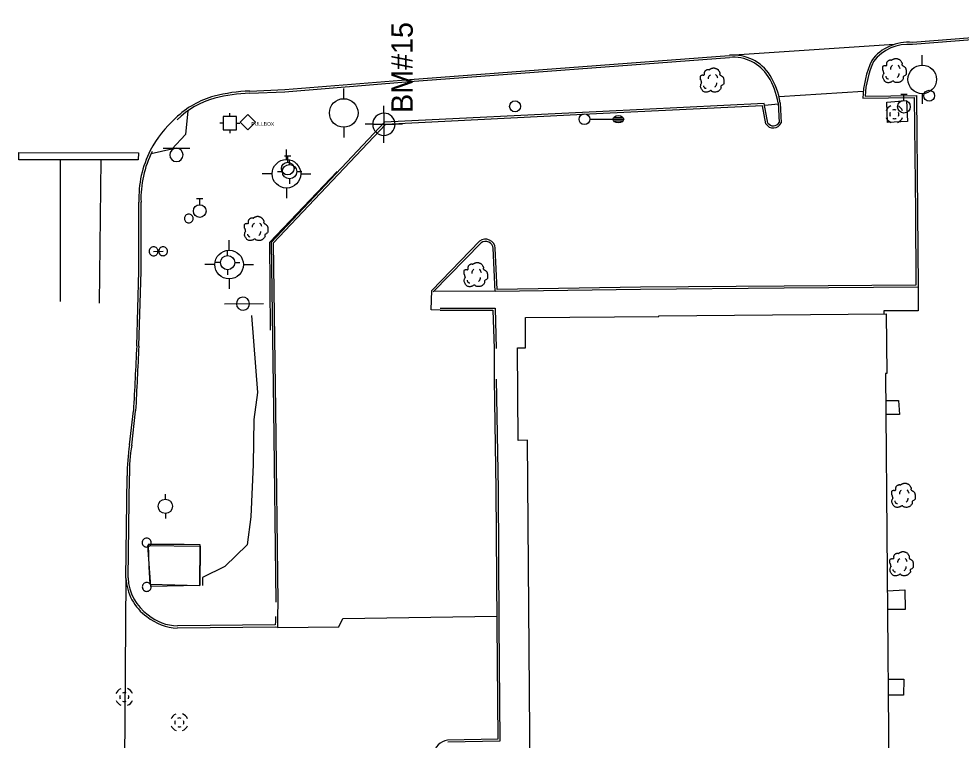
# Model space of a CAD drawing. Extents: x 2145380 to 2156929, y 139568 to 149130.
# Drawn here: x 2145641 to 2145904.9, y 142715.7 to 142917.6 of the extents above; entities that cross this region are included whole.
import ezdxf

# ---------------------------------------------------------------- set-up
doc = ezdxf.new("R2010")
doc.units = 0
for name, color, linetype in [('Default', 7, 'Continuous'), ('SURV_Benchmark', 7, 'Continuous'), ('SURV_Text', 7, 'Continuous'), ('TOPO_Asphalt', 7, 'Continuous'), ('TOPO_Building', 7, 'Continuous'), ('TOPO_Concrete', 7, 'Continuous'), ('TOPO_Curb Back', 7, 'Continuous'), ('TOPO_DRAIN_Inlet Grate', 7, 'Continuous'), ('TOPO_DRAIN_Manhole', 7, 'Continuous'), ('TOPO_Flowline', 7, 'Continuous'), ('TOPO_Light Pole', 7, 'Continuous'), ('TOPO_Misc', 7, 'Continuous'), ('TOPO_Misc Line', 7, 'Continuous'), ('TOPO_Power Pole', 7, 'Continuous'), ('TOPO_Power Pullbox', 7, 'Continuous'), ('TOPO_Sidewalk', 7, 'Continuous'), ('TOPO_Sign', 7, 'Continuous'), ('TOPO_Traffic Signal', 7, 'Continuous'), ('TOPO_Tree', 7, 'Continuous'), ('TOPO_Wall Freestanding', 7, 'Continuous'), ('TOPO_Water Fire Hydrant', 7, 'Continuous'), ('TOPO_Water Meter', 7, 'Continuous'), ('TOPO_Water Valve', 7, 'Continuous')]:
    doc.layers.add(name, color=color, linetype=linetype)

# ---------------------------------------------------------------- blocks, each defined once
blk = doc.blocks.new('MHEXST')
at = {"layer": 'TOPO_DRAIN_Manhole'}
for centre, radius, start, end in [((-0.1, 0.3), 12.7, 112.9748, 158.2636), ((-0.1, 0.1), 6.35, 157.9722, 204.161), ((-0.1, 0.1), 6.35, 66.1941, 113.691), ((-0.1, 0.3), 12.7, 22.0744, 68.6991), ((-0.1, 0.1), 6.35, 336.8023, 21.4046), ((-0.1, 0.3), 12.7, 202.6921, 248.1938), ((-0.1, 0.1), 6.35, 248.5791, 293.1995), ((-0.1, 0.3), 12.7, 291.7963, 337.3032)]:
    blk.add_arc(centre, radius, start, end, dxfattribs=at)
blk = doc.blocks.new('TRFSIG')
at = {"layer": 'TOPO_Traffic Signal'}
for p, q in [((0.04, 4.66), (0.04, 7.04)), ((-4.7, -0.09), (-7.08, -0.09)), ((0.04, -4.83), (0.04, -7.22)), ((4.79, -0.09), (7.17, -0.09))]:
    blk.add_line(p, q, dxfattribs=at)
blk.add_lwpolyline([(-4.7, -4.85), (4.81, -4.83), (4.79, 4.67), (-4.72, 4.66), (-4.7, -4.85)], dxfattribs=at)
blk = doc.blocks.new('FIRHYD')
at = {"layer": 'TOPO_Water Fire Hydrant'}
for p, q in [((-0.02, 10.16), (-0.03, 17.34)), ((10.16, 0.02), (17.34, 0.03)), ((-10.16, -0.02), (-17.34, -0.03)), ((0.02, -10.16), (0.03, -17.34))]:
    blk.add_line(p, q, dxfattribs=at)
blk.add_circle((0, 0), 10.16, dxfattribs=at)
blk = doc.blocks.new('POST')
at = {"layer": 'TOPO_Misc'}
for start, end in [(89.99996, 180.00004), (179.99996, 270.00004), (359.99996, 90.00004), (269.99996, 0.00004)]:
    blk.add_arc((-0.01, 0.03), 3.16, start, end, dxfattribs=at)
blk = doc.blocks.new('POWPOL')
at = {"layer": 'TOPO_Power Pole'}
for p, q in [((0, 10.16), (0, 17.34)), ((0, -10.16), (0, -17.34))]:
    blk.add_line(p, q, dxfattribs=at)
blk.add_circle((0, 0), 10.16, dxfattribs=at)
blk = doc.blocks.new('LP')
at = {"layer": 'TOPO_Light Pole'}
blk.add_line((3.81, 0), (20.32, 0), dxfattribs=at)
for points in [[(20.32, 0), (27.94, 0)], [(20.32, 0), (23.5, 0)], [(20.83, 1.27), (27.43, 1.27)], [(20.83, 1.27), (23.5, 1.27)], [(23.71, 1.27), (27.43, 1.27)], [(23.71, 0), (27.94, 0)], [(20.83, -1.27), (27.43, -1.27)], [(20.83, -1.27), (23.5, -1.27)], [(23.71, -1.27), (27.43, -1.27)]]:
    blk.add_lwpolyline(points, dxfattribs=at)
blk.add_circle((0, 0), 3.81, dxfattribs=at)
blk.add_ellipse((24.13, 0), major_axis=(3.81, 0), ratio=0.666667, dxfattribs=at)
blk = doc.blocks.new('TREE')
at = {"layer": 'TOPO_Tree'}
for points in [[(-14.1, -0.4), (-14.2, 0.5), (-14.4, 1.4), (-14.6, 2.3), (-14.8, 3.2), (-15.5, 4), (-15.7, 4.9), (-15.8, 5.6), (-15.7, 6.3), (-15.7, 7), (-15.6, 7.9), (-15.7, 8.8), (-15.1, 9.7), (-14.6, 10.4), (-13.8, 10.5), (-13, 10.7), (-12.2, 11), (-11.1, 10), (-10.4, 10.7), (-9.4, 11.7), (-10.3, 13.3), (-9.8, 14.4), (-9.6, 15.1), (-9.3, 15.9), (-8.8, 16.5), (-8.2, 17.3), (-7.5, 17.7), (-6.7, 18.1), (-6.1, 18.4), (-5.6, 18.6), (-5.1, 18.7), (-4.5, 18.7), (-4, 18.5), (-3.5, 18.1)], [(-3.5, 17.6), (-3.1, 18.3), (-2.6, 18.8), (-1.9, 19.2), (-1, 19.7), (-0.2, 20), (0.7, 20.2), (1.6, 20.5), (2.5, 20.8), (3.4, 20.8), (4.1, 20.7), (4.8, 20.5), (5.5, 20.2), (6.4, 19.9), (7.3, 19.7), (8.2, 19.2), (9.4, 18.4), (10, 17.2), (10.8, 16), (11.2, 15.3), (11.6, 14.6), (11.9, 13.9), (12.2, 13.1), (11.4, 12), (11.9, 11.2), (12, 11), (12.2, 10.9), (12.4, 10.7), (12.9, 10.4), (13.5, 10), (14, 9.7), (14.7, 9.2), (15.4, 8.7), (16.1, 8.1), (16.7, 7.5), (16.9, 6.7), (17.1, 6), (17.6, 4.4), (17.7, 2.8), (17.7, 1.2), (17.7, -0.2), (17.8, -2.2), (16.6, -3), (15.5, -3.8), (14.3, -4.6), (13.2, -5.3)], [(13.2, -5.3), (13.3, -5.8), (13.4, -6.3), (13.4, -6.7), (13.8, -8.5), (12.2, -10), (10.8, -11.5), (10, -12.3), (9.1, -12.8), (8.2, -13.1), (6, -13.8), (3.3, -13.6), (1.3, -13.1), (0.5, -12.9), (-0.1, -11.4), (-0.8, -11.5), (-2, -11.6), (-3.3, -12.8), (-4.5, -13.1), (-6.1, -13.5), (-7.8, -14), (-9.3, -13.6), (-11.4, -13.1), (-12.8, -11.4), (-14.1, -9.4), (-15.3, -7.3), (-15.6, -5.1), (-15.1, -3), (-14.9, -1.9), (-13.9, -0.8), (-13.5, 0.1)], [(-4.2, 5.1), (-4.5, 6.1), (-4.3, 7.2), (-3.8, 8.2), (-3.3, 9.3), (-2.7, 10.3), (-1.6, 11)], [(5.9, 11.2), (6.5, 10.7), (7, 10.2), (7.4, 9.5), (7.9, 8.6), (8.3, 7.6), (8.5, 6.6)], [(-11.4, -4.5), (-11.5, -5.4), (-11, -6.3), (-10.1, -7.2), (-9.3, -8), (-8.5, -8.3), (-7.7, -8.1)], [(4.8, -6.3), (5.7, -5.7), (6.3, -4.9), (6.8, -3.9), (7.4, -2.8), (7.6, -1.7), (7.5, -0.6)]]:
    blk.add_open_spline(points, degree=3, dxfattribs=at)
blk = doc.blocks.new('pulbox')
at = {"layer": 'Default'}
blk.add_lwpolyline([(-5.38, -0.01), (-0.02, 5.42), (5.4, 0.06), (0.05, -5.36), (-5.38, -0.01)], dxfattribs=at)
blk.add_text('PULLBOX', height=2.54, dxfattribs=at).set_placement((2.54, -2.54))
blk = doc.blocks.new('WTRMTR')
at = {"layer": 'Default'}
blk.add_circle((0, 0), 3.89, dxfattribs=at)
blk = doc.blocks.new('WATVAL')
at = {"layer": 'Default'}
for p, q in [((-2.25, 9), (2.25, 9)), ((0, 4.5), (0, 9))]:
    blk.add_line(p, q, dxfattribs=at)
blk.add_circle((0, 0), 4.5, dxfattribs=at)
blk = doc.blocks.new('BM')
at = {"layer": 'SURV_Benchmark'}
for p, q in [((0, 2.49), (0, 4.15)), ((-2.49, 0), (-4.16, 0)), ((4.16, 0), (2.49, 0)), ((0, -4.16), (0, -2.49))]:
    blk.add_line(p, q, dxfattribs=at)
for points in [[(0, 2.49), (0, 2.49), (0, 0), (2.49, 0), (2.49, 0), (2.49, 0)], [(0, 2.49), (0, 2.49), (0, 0), (2.49, 0), (2.49, 0), (2.49, 0), (2.49, 0)], [(-2.5, 0), (-2.49, 0), (0, 0), (0, -2.49), (0, -2.49)], [(-2.5, 0), (-2.49, 0), (0, 0), (0, -2.49), (0, -2.49)]]:
    blk.add_lwpolyline(points, dxfattribs=at)
for start, end in [(90.0638, 180.0068), (0.0638, 90.0068), (0.0638, 90.0068), (180.0638, 270.0068), (180.0638, 270.0068), (269.9472, 359.9927)]:
    blk.add_arc((0, 0), 2.5, start, end, dxfattribs=at)

msp = doc.modelspace()

# ---------------------------------------------------------------- linework, layer by layer
at = {"layer": 'TOPO_Asphalt'}
for p, q in [((2145886.13, 142910.45), (2145841.37, 142907.47)), ((2145877.51, 142897.29), (2145853.93, 142895.76)), ((2145774.14, 142825.35), (2145774.11, 142816.75)), ((2145671.02, 142761.1), (2145670.5, 142699.12)), ((2145713.58, 142754.35), (2145713.49, 142750.35))]:
    msp.add_line(p, q, dxfattribs=at)
for points in [[(2145759.07, 142836.04), (2145756.5, 142836.19), (2145756.67, 142841.6)], [(2145713.48, 142747.28), (2145730.63, 142747.43), (2145731.81, 142749.72), (2145774.89, 142750.39)]]:
    msp.add_lwpolyline(points, dxfattribs=at)
msp.add_arc((2145705.41, 142866.44), 31.07, 131.2509, 152.4834, dxfattribs=at)
at = {"layer": 'TOPO_Building'}
msp.add_lwpolyline([(2145884.64, 142706.75), (2145784.22, 142705.97), (2145783.49, 142799.65), (2145780.88, 142799.63), (2145780.68, 142825.53), (2145782.96, 142825.55), (2145782.9, 142834.03), (2145820.28, 142834.32), (2145820.28, 142834.52), (2145883.96, 142835.02), (2145884.09, 142818.36), (2145883.77, 142818.35)], close=True, dxfattribs=at)
at = {"layer": 'TOPO_Concrete'}
for p in [(2145849.96, 142893.38), (2145853.67, 142893.7)]:
    msp.add_line(p, (2145849.97, 142893.35), dxfattribs=at)
for points in [[(2145884.29, 142888.65), (2145884.12, 142894.3), (2145889.62, 142894.74), (2145889.85, 142888.86), (2145884.29, 142888.65)], [(2145691.76, 142759.04), (2145678.01, 142758.73), (2145677.16, 142770.2), (2145691.84, 142769.99), (2145691.76, 142759.04)], [(2145687.34, 142770.51), (2145677.29, 142770.48), (2145677.43, 142764.27), (2145677.71, 142759.42), (2145691.77, 142759.01)]]:
    msp.add_lwpolyline(points, dxfattribs=at)
at = {"layer": 'TOPO_Curb Back'}
for points in [[(2146086.5, 142923.91), (2146062.14, 142922.81), (2146006.06, 142919.37), (2145953.33, 142915.85), (2145891.26, 142911.02)], [(2146086.5, 142923.31), (2146062.17, 142922.21), (2146006.1, 142918.78), (2145953.37, 142915.25), (2145891.26, 142910.41)], [(2145705.69, 142897.41), (2145715.49, 142897.82), (2145750.51, 142900.64), (2145840, 142907.41)], [(2145705.71, 142896.81), (2145715.53, 142897.22), (2145750.55, 142900.04), (2145840.06, 142906.82)], [(2145878.01, 142895.99), (2145892.37, 142896.17), (2145892.74, 142863.48), (2145892.85, 142842.52), (2145855.35, 142842.22), (2145815.14, 142841.9), (2145774.4, 142841.27), (2145773.86, 142853.39)], [(2145850.79, 142888.46), (2145849.77, 142893.91), (2145804.61, 142891.73), (2145743.47, 142888.67), (2145711.71, 142855.05), (2145712.36, 142808.25), (2145712.98, 142754.34)], [(2145850.22, 142888.24), (2145849.28, 142893.29), (2145804.64, 142891.13), (2145743.74, 142888.08), (2145712.31, 142854.81), (2145712.96, 142808.26), (2145713.58, 142754.35)], [(2145877.38, 142895.38), (2145891.78, 142895.57), (2145892.14, 142863.48), (2145892.25, 142843.11), (2145855.35, 142842.82), (2145815.14, 142842.5), (2145774.97, 142841.88), (2145774.46, 142853.43)], [(2145853.65, 142894.1), (2145853.93, 142888.65)], [(2145854.25, 142894.16), (2145854.54, 142888.53)], [(2145711.55, 142830.49), (2145711.32, 142855.13), (2145730.22, 142874.89)], [(2145674.05, 142826.07), (2145674.67, 142847.01), (2145674.66, 142866.3)], [(2145674.65, 142826.04), (2145675.27, 142847), (2145675.26, 142866.31)], [(2145770.08, 142855.38), (2145756.67, 142841.6)], [(2145770.48, 142854.93), (2145757.1, 142841.18)], [(2145759.07, 142836.64), (2145774.39, 142836.67), (2145774.74, 142825.37)], [(2145759.07, 142836.04), (2145773.81, 142836.07), (2145774.14, 142825.35)], [(2145774.11, 142816.75), (2145774.65, 142785.86), (2145774.9, 142748.25), (2145775.16, 142716.03), (2145761.11, 142715.71)], [(2145774.71, 142816.76), (2145775.25, 142785.87), (2145775.5, 142748.26), (2145775.76, 142715.44), (2145761.17, 142715.11)], [(2145672.06, 142798.38), (2145673.14, 142807.9)], [(2145672.65, 142798.3), (2145673.74, 142807.85)], [(2145671.02, 142761.1), (2145671.4, 142789.68)], [(2145671.62, 142761.11), (2145672, 142789.68)], [(2145713.5, 142750.31), (2145713.48, 142747.28), (2145712.97, 142747.32), (2145685.42, 142747.1)], [(2145712.9, 142750.32), (2145712.9, 142748.9), (2145712.86, 142747.98), (2145685.43, 142747.7)]]:
    msp.add_lwpolyline(points, dxfattribs=at)
for centre, radius, start, end in [((2145890.08, 142898.28), 12.8, 84.6897, 142.941), ((2145890.08, 142898.28), 12.2, 84.4518, 142.6291), ((2145841.16, 142895.41), 12.06, 31.8502, 95.4973), ((2145841.16, 142895.41), 11.46, 31.8468, 95.5275), ((2145905.51, 142894.38), 28.15, 155.6481, 177.9548), ((2145905.51, 142894.38), 27.55, 155.788, 176.6443), ((2145834.14, 142890.99), 19.76, 9.0341, 31.9817), ((2145834.14, 142890.99), 20.36, 8.9444, 31.9797), ((2145702.16, 142872.13), 24.69, 105.0623, 134.2848), ((2145707.07, 142852.94), 44.49, 91.7794, 104.7442), ((2145707.07, 142852.94), 43.89, 91.7752, 104.742), ((2145702.16, 142872.13), 24.09, 105.0663, 134.2848), ((2145852.31, 142889.5), 2.43, 211.1477, 336.5758), ((2145852.31, 142889.5), 1.83, 214.3157, 332.4691), ((2145704.6, 142867.3), 29.96, 153.2161, 181.9143), ((2145704.6, 142867.3), 29.36, 153.2161, 181.9334), ((2145771.74, 142853.22), 2.72, 4.3097, 127.5899), ((2145771.74, 142853.22), 2.12, 4.5437, 126.5018), ((2161048.92, 142043.63), 15394.76, 177.086696, 177.154392), ((2161048.93, 142043.63), 15394.17, 177.086673, 177.154463), ((2145721.13, 142790.33), 49.73, 170.6762, 180.7386), ((2145721.13, 142790.33), 49.13, 170.659, 180.7478), ((2145685.07, 142761.73), 14.06, 182.5625, 234.441), ((2145685.07, 142761.73), 13.46, 182.6359, 234.5179), ((2145685.94, 142761.46), 13.78, 230.9156, 267.8614), ((2145685.94, 142761.46), 14.38, 230.9908, 267.9161), ((2145761.93, 142710.85), 4.93, 99.5713, 169.4602)]:
    msp.add_arc(centre, radius, start, end, dxfattribs=at)
at = {"layer": 'TOPO_DRAIN_Inlet Grate'}
msp.add_line((2145678.79, 142852.54), (2145681.45, 142852.55), dxfattribs=at)
at = {"layer": 'TOPO_Flowline'}
msp.add_lwpolyline([(2145706.15, 142834.57), (2145707.84, 142813.02), (2145706.89, 142805.44), (2145706.62, 142792.9), (2145705.97, 142778.22), (2145704.97, 142770.4), (2145698.73, 142764.31), (2145692.47, 142761.25), (2145692.48, 142758.96)], dxfattribs=at)
at = {"layer": 'TOPO_Misc Line'}
for p, q in [((2145652.61, 142878.17), (2145652.64, 142838.47)), ((2145664, 142878.16), (2145663.55, 142838))]:
    msp.add_line(p, q, dxfattribs=at)
msp.add_lwpolyline([(2145641.05, 142880.2), (2145674.51, 142880.15), (2145674.5, 142878.14), (2145641.05, 142878.19)], close=True, dxfattribs=at)
at = {"layer": 'TOPO_Sidewalk'}
msp.add_line((2145774.4, 142841.27), (2145757.32, 142841.4), dxfattribs=at)
for points in [[(2145688.33, 142891.85), (2145687.71, 142885.28), (2145683.92, 142881.18), (2145678.06, 142879.86)], [(2145892.85, 142842.52), (2145892.92, 142835.87), (2145883.23, 142835.92), (2145883.23, 142835.01)], [(2145883.83, 142810.75), (2145887.34, 142810.78), (2145887.61, 142806.89), (2145883.86, 142806.86)], [(2145884.25, 142757.51), (2145889.14, 142757.83), (2145889.25, 142752.3), (2145884.29, 142752.3)], [(2145884.44, 142732.77), (2145888.86, 142732.8), (2145888.82, 142728.29), (2145884.48, 142728.26)]]:
    msp.add_lwpolyline(points, dxfattribs=at)
at = {"layer": 'TOPO_Sign'}
for points in [[(2145681.43, 142881.4), (2145688.93, 142881.4)], [(2145685.18, 142881.4), (2145685.18, 142881.4)], [(2145683.31, 142879.53), (2145683.31, 142879.53)], [(2145685.18, 142877.66), (2145685.18, 142877.66)], [(2145687.05, 142879.53), (2145687.05, 142879.53)], [(2145698.67, 142837.88), (2145709.55, 142837.94)]]:
    msp.add_lwpolyline(points, dxfattribs=at)
for centre, radius, start, end in [((2145685.18, 142879.53), 1.87, 90, 180), ((2145685.18, 142879.53), 1.87, 360, 90), ((2145685.18, 142879.53), 1.87, 180, 270), ((2145685.18, 142879.53), 1.87, 270, 0), ((2145703.81, 142837.9), 1.84, 47.4196, 227.4196), ((2145703.81, 142837.9), 1.84, 227.4196, 47.4196)]:
    msp.add_arc(centre, radius, start, end, dxfattribs=at)
at = {"layer": 'TOPO_Wall Freestanding'}
msp.add_lwpolyline([(2145691.77, 142759.01), (2145691.84, 142770.39), (2145687.34, 142770.51)], dxfattribs=at)

# ---------------------------------------------------------------- block references
at = {"layer": 'SURV_Benchmark', "xscale": 1.25, "yscale": 1.25}
msp.add_blockref('BM', (2145743.27, 142888.11), dxfattribs=at)
at = {"layer": 'TOPO_DRAIN_Manhole', "xscale": 0.19685000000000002, "yscale": 0.19685000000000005}
for p in [(2145886.23, 142890.9), (2145670.59, 142727.74), (2145686.01, 142720.65)]:
    msp.add_blockref('MHEXST', p, dxfattribs=at)
at = {"layer": 'TOPO_Light Pole', "xscale": 0.39370000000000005, "yscale": 0.3937000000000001}
msp.add_blockref('LP', (2145799.42, 142889.53), dxfattribs=at)
at = {"layer": 'TOPO_Misc', "xscale": 0.39370000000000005, "yscale": 0.3937000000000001}
for p in [(2145688.64, 142861.73), (2145678.79, 142852.54), (2145681.45, 142852.55), (2145676.84, 142770.99), (2145676.87, 142758.59)]:
    msp.add_blockref('POST', p, dxfattribs=at)
at = {"layer": 'TOPO_Power Pole'}
for p, xscale, yscale in [((2145894.02, 142900.67), 0.39370000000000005, 0.3937000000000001), ((2145732.02, 142891.28), 0.39370000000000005, 0.3937000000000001), ((2145682.08, 142781.17), 0.19685000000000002, 0.19685000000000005)]:
    msp.add_blockref('POWPOL', p, dxfattribs=dict(at, xscale=xscale, yscale=yscale))
at = {"layer": 'TOPO_Power Pullbox', "xscale": 0.39370000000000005, "yscale": 0.3937000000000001}
msp.add_blockref('pulbox', (2145705.16, 142888.71), dxfattribs=at)
at = {"layer": 'TOPO_Traffic Signal', "xscale": 0.39370000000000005, "yscale": 0.3937000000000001}
msp.add_blockref('TRFSIG', (2145700.11, 142888.46), dxfattribs=at)
at = {"layer": 'TOPO_Tree', "xscale": 0.19685000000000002, "yscale": 0.19685000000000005}
for p in [(2145886.05, 142902.46), (2145835, 142899.8), (2145707.31, 142858.26), (2145768.81, 142845.35), (2145888.57, 142783.57), (2145888.04, 142764.41)]:
    msp.add_blockref('TREE', p, dxfattribs=at)
at = {"layer": 'TOPO_Water Fire Hydrant'}
for p, xscale, yscale in [((2145715.99, 142874.25), 0.39370000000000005, 0.3937000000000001), ((2145716.86, 142874.85), 0.19685000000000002, 0.19685000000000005), ((2145699.94, 142848.83), 0.39370000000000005, 0.3937000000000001), ((2145699.5, 142849.39), 0.19685000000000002, 0.19685000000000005)]:
    msp.add_blockref('FIRHYD', p, dxfattribs=dict(at, xscale=xscale, yscale=yscale))
at = {"layer": 'TOPO_Water Meter', "xscale": 0.39370000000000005, "yscale": 0.3937000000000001}
for p in [(2145895.96, 142896.09), (2145780.01, 142893.13)]:
    msp.add_blockref('WTRMTR', p, dxfattribs=at)
at = {"layer": 'TOPO_Water Valve', "xscale": 0.39370000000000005, "yscale": 0.3937000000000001}
for p in [(2145888.89, 142893.04), (2145716.36, 142875.73), (2145691.69, 142863.82)]:
    msp.add_blockref('WATVAL', p, dxfattribs=at)

# ---------------------------------------------------------------- texts
at = {"layer": 'SURV_Text'}
msp.add_text('BM#15', height=6, rotation=90, dxfattribs=at).set_placement((2145751.36, 142891.29))

doc.saveas('drawing.dxf')
